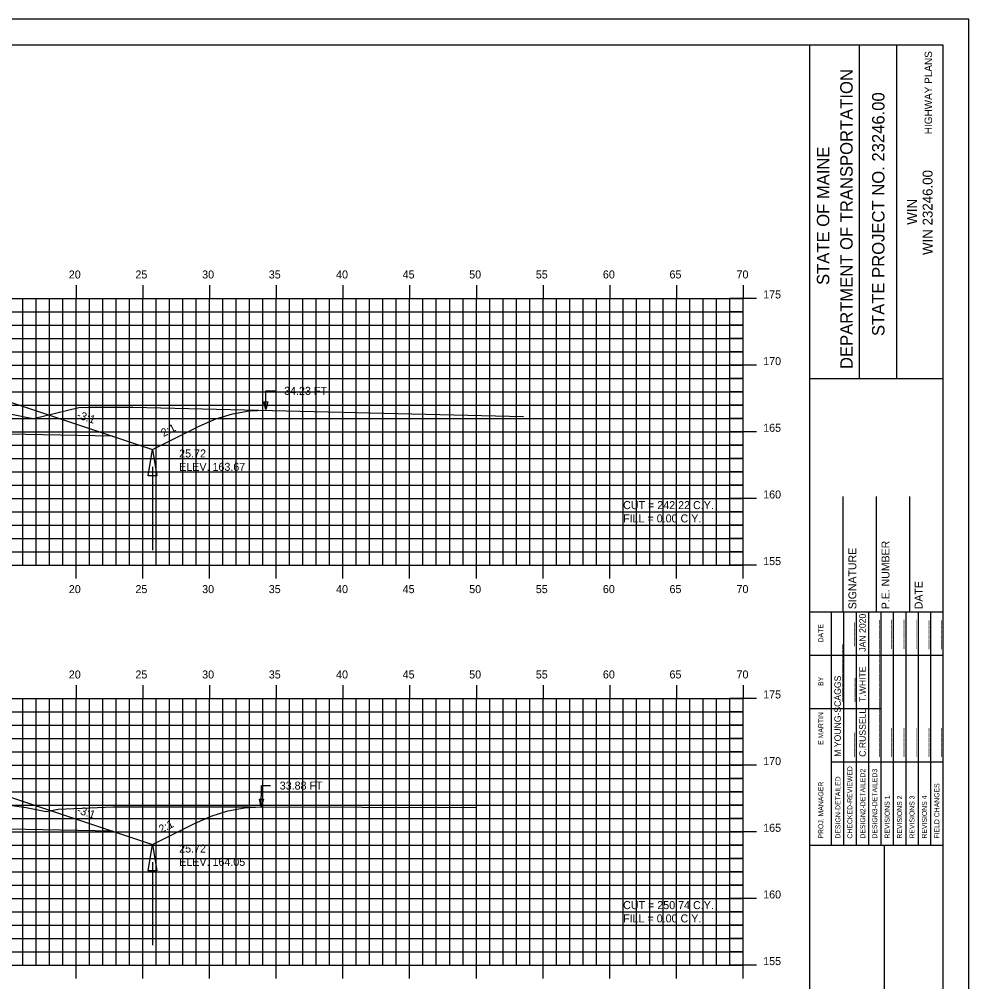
# Model space of a CAD drawing. Extents: x 1142089 to 1142259, y 608981 to 609091.
# Drawn here: x 1142188.3 to 1142259.4, y 609019.1 to 609091.3 of the extents above; entities that cross this region are included whole.
import ezdxf

# ---------------------------------------------------------------- set-up
doc = ezdxf.new("R2010")
doc.units = 0
for name, color, linetype in [('ANNOTATION', 7, 'Continuous'), ('BORDER', 7, 'Continuous'), ('D_Drainage_Ditch_Line', 7, 'Continuous'), ('D_Roadway_SlopeLines', 7, 'Continuous'), ('D_Roadway_SubGrade', 7, 'Continuous'), ('D_Text_Standard', 7, 'Continuous'), ('H_V ANNOTATION', 7, 'Continuous'), ('HIGHWAY_TITLE', 7, 'Continuous'), ('MAJOR', 7, 'Continuous'), ('MINOR', 7, 'Continuous'), ('PLOT BOUNDARY', 7, 'Continuous'), ('S_Roadway_Centerline', 7, 'Continuous')]:
    doc.layers.add(name, color=color, linetype=linetype)

msp = doc.modelspace()

# ---------------------------------------------------------------- linework, layer by layer
for points in [[(1142137.828, 609062.265), (1142139.078, 609062.182), (1142140.328, 609061.943), (1142141.578, 609061.55), (1142142.828, 609061.002), (1142146.816, 609059.009), (1142149.816, 609060.009), (1142157.539, 609062.583), (1142157.54, 609062.583), (1142161.54, 609062.743), (1142172.54, 609062.963), (1142183.54, 609062.743), (1142187.54, 609062.583), (1142195.264, 609060.009), (1142198.264, 609059.009), (1142201.765, 609060.76), (1142203.015, 609061.303), (1142204.265, 609061.682), (1142205.515, 609061.898), (1142206.765, 609061.95)], [(1142136.708, 609033.172), (1142137.958, 609033.099), (1142139.208, 609032.868), (1142140.458, 609032.48), (1142141.708, 609031.934), (1142146.816, 609029.38), (1142149.816, 609030.38), (1142157.539, 609032.955), (1142157.54, 609032.955), (1142161.54, 609033.115), (1142172.54, 609033.335), (1142183.54, 609033.115), (1142187.54, 609032.955), (1142195.264, 609030.38), (1142198.264, 609029.38), (1142201.423, 609030.96), (1142202.673, 609031.506), (1142203.923, 609031.896), (1142205.173, 609032.129), (1142206.423, 609032.206)]]:
    msp.add_lwpolyline(points)
at = {"layer": 'BORDER'}
for p, q in [((1142247.541, 608984.335), (1142247.541, 609089.335)), ((1142251.269, 609064.332), (1142251.269, 609089.332)), ((1142254.064, 609064.332), (1142254.064, 609089.332)), ((1142247.541, 609064.329), (1142257.541, 609064.329)), ((1142250.041, 609046.838), (1142250.041, 609055.485)), ((1142252.541, 609046.838), (1142252.541, 609055.485)), ((1142255.041, 609046.838), (1142255.041, 609055.485)), ((1142247.541, 609046.838), (1142257.541, 609046.838)), ((1142247.541, 609029.338), (1142257.541, 609029.338)), ((1142253.132, 608994.338), (1142253.132, 609029.338))]:
    msp.add_line(p, q, dxfattribs=at)
msp.add_lwpolyline([(1142097.541, 608984.335), (1142257.541, 608984.335), (1142257.541, 609089.335), (1142097.541, 609089.335)], close=True, dxfattribs=at)
for points in [[(1142249.155, 609043.588), (1142249.155, 609046.838)], [(1142250.088, 609029.341), (1142250.088, 609046.838)], [(1142251.02, 609046.838), (1142251.02, 609029.341)], [(1142251.951, 609029.341), (1142251.951, 609046.838)], [(1142252.883, 609029.341), (1142252.883, 609046.838)], [(1142253.815, 609029.341), (1142253.815, 609046.838)], [(1142254.746, 609029.341), (1142254.746, 609046.838)], [(1142255.678, 609029.341), (1142255.678, 609046.838)], [(1142256.61, 609029.341), (1142256.61, 609046.838)], [(1142249.156, 609029.341), (1142249.156, 609046.132)], [(1142247.541, 609043.588), (1142257.541, 609043.588)], [(1142247.541, 609039.588), (1142249.156, 609039.588)], [(1142249.155, 609039.588), (1142252.882, 609039.588)], [(1142249.155, 609035.588), (1142257.541, 609035.588)]]:
    msp.add_lwpolyline(points, dxfattribs=at)
at = {"layer": 'D_Drainage_Ditch_Line'}
for p, q in [((1142198.264, 609057.697), (1142198.263, 609051.453)), ((1142198.264, 609028.068), (1142198.263, 609021.824))]:
    msp.add_line(p, q, dxfattribs=at)
for points in [[(1142198.592, 609057.04), (1142197.936, 609057.04), (1142198.264, 609059.009)], [(1142198.592, 609027.412), (1142197.936, 609027.412), (1142198.264, 609029.38)]]:
    msp.add_lwpolyline(points, close=True, dxfattribs=at)
at = {"layer": 'D_Roadway_SlopeLines'}
for points in [[(1142198.264, 609059.009), (1142201.765, 609060.76), (1142203.015, 609061.303), (1142204.265, 609061.682), (1142205.515, 609061.898), (1142206.765, 609061.95)], [(1142195.264, 609060.009), (1142198.264, 609059.009)], [(1142198.264, 609029.38), (1142201.423, 609030.96), (1142202.673, 609031.506), (1142203.923, 609031.896), (1142205.173, 609032.129), (1142206.423, 609032.206)], [(1142195.264, 609030.38), (1142198.264, 609029.38)]]:
    msp.add_lwpolyline(points, dxfattribs=at)
at = {"layer": 'D_Roadway_SubGrade'}
for points in [[(1142183.54, 609062.327), (1142183.54, 609062.493), (1142187.54, 609062.333), (1142187.54, 609062.583), (1142187.54, 609062.583), (1142195.264, 609060.009), (1142183.54, 609060.243)], [(1142183.54, 609032.698), (1142183.54, 609032.865), (1142187.54, 609032.705), (1142187.54, 609032.955), (1142187.54, 609032.955), (1142195.264, 609030.38), (1142183.54, 609030.615)]]:
    msp.add_lwpolyline(points, close=True, dxfattribs=at)
at = {"layer": 'D_Text_Standard'}
for points in [[(1142206.765, 609062.01), (1142206.771, 609063.407), (1142207.451, 609063.407)], [(1142206.423, 609032.21), (1142206.442, 609033.799), (1142207.122, 609033.799)]]:
    msp.add_lwpolyline(points, dxfattribs=at)
for points in [[(1142206.765, 609062.01), (1142206.622, 609062.592), (1142206.913, 609062.591)], [(1142206.423, 609032.21), (1142206.284, 609032.793), (1142206.575, 609032.79)]]:
    msp.add_lwpolyline(points, close=True, dxfattribs=at)
at = {"layer": 'MAJOR'}
for p, q in [((1142192.54, 609071.337), (1142192.54, 609070.335)), ((1142197.54, 609071.337), (1142197.54, 609070.335)), ((1142202.54, 609071.337), (1142202.54, 609070.335)), ((1142207.54, 609071.337), (1142207.54, 609070.335)), ((1142212.54, 609071.337), (1142212.54, 609070.335)), ((1142217.54, 609071.337), (1142217.54, 609070.335)), ((1142222.54, 609071.337), (1142222.54, 609070.335)), ((1142227.54, 609071.337), (1142227.54, 609070.335)), ((1142232.54, 609071.337), (1142232.54, 609070.335)), ((1142237.54, 609071.337), (1142237.54, 609070.335)), ((1142242.54, 609071.337), (1142242.54, 609070.335)), ((1142102.54, 609070.335), (1142242.54, 609070.335)), ((1142102.54, 609070.335), (1142242.54, 609070.335)), ((1142192.54, 609050.335), (1142192.54, 609070.335)), ((1142197.54, 609050.335), (1142197.54, 609070.335)), ((1142202.54, 609050.335), (1142202.54, 609070.335)), ((1142207.54, 609050.335), (1142207.54, 609070.335)), ((1142212.54, 609050.335), (1142212.54, 609070.335)), ((1142217.54, 609050.335), (1142217.54, 609070.335)), ((1142222.54, 609050.335), (1142222.54, 609070.335)), ((1142227.54, 609050.335), (1142227.54, 609070.335)), ((1142232.54, 609050.335), (1142232.54, 609070.335)), ((1142237.54, 609050.335), (1142237.54, 609070.335)), ((1142243.542, 609070.335), (1142241.538, 609070.335)), ((1142242.54, 609050.335), (1142242.54, 609070.335)), ((1142242.54, 609050.335), (1142242.54, 609070.335)), ((1142102.54, 609065.335), (1142242.54, 609065.335)), ((1142243.542, 609065.335), (1142241.538, 609065.335)), ((1142102.54, 609060.335), (1142242.54, 609060.335)), ((1142243.542, 609060.335), (1142241.538, 609060.335)), ((1142102.54, 609055.335), (1142242.54, 609055.335)), ((1142243.542, 609055.335), (1142241.538, 609055.335)), ((1142102.54, 609050.335), (1142242.54, 609050.335)), ((1142102.54, 609050.335), (1142242.54, 609050.335)), ((1142192.54, 609049.333), (1142192.54, 609050.335)), ((1142197.54, 609049.333), (1142197.54, 609050.335)), ((1142202.54, 609049.333), (1142202.54, 609050.335)), ((1142207.54, 609049.333), (1142207.54, 609050.335)), ((1142212.54, 609049.333), (1142212.54, 609050.335)), ((1142217.54, 609049.333), (1142217.54, 609050.335)), ((1142222.54, 609049.333), (1142222.54, 609050.335)), ((1142227.54, 609049.333), (1142227.54, 609050.335)), ((1142232.54, 609049.333), (1142232.54, 609050.335)), ((1142237.54, 609049.333), (1142237.54, 609050.335)), ((1142243.542, 609050.335), (1142241.538, 609050.335)), ((1142242.54, 609049.333), (1142242.54, 609050.335)), ((1142192.54, 609041.337), (1142192.54, 609040.335)), ((1142197.54, 609041.337), (1142197.54, 609040.335)), ((1142202.54, 609041.337), (1142202.54, 609040.335)), ((1142207.54, 609041.337), (1142207.54, 609040.335)), ((1142212.54, 609041.337), (1142212.54, 609040.335)), ((1142217.54, 609041.337), (1142217.54, 609040.335)), ((1142222.54, 609041.337), (1142222.54, 609040.335)), ((1142227.54, 609041.337), (1142227.54, 609040.335)), ((1142232.54, 609041.337), (1142232.54, 609040.335)), ((1142237.54, 609041.337), (1142237.54, 609040.335)), ((1142242.54, 609041.337), (1142242.54, 609040.335)), ((1142102.54, 609040.335), (1142242.54, 609040.335)), ((1142102.54, 609040.335), (1142242.54, 609040.335)), ((1142192.54, 609020.335), (1142192.54, 609040.335)), ((1142197.54, 609020.335), (1142197.54, 609040.335)), ((1142202.54, 609020.335), (1142202.54, 609040.335)), ((1142207.54, 609020.335), (1142207.54, 609040.335)), ((1142212.54, 609020.335), (1142212.54, 609040.335)), ((1142217.54, 609020.335), (1142217.54, 609040.335)), ((1142222.54, 609020.335), (1142222.54, 609040.335)), ((1142227.54, 609020.335), (1142227.54, 609040.335)), ((1142232.54, 609020.335), (1142232.54, 609040.335)), ((1142237.54, 609020.335), (1142237.54, 609040.335)), ((1142243.542, 609040.335), (1142241.538, 609040.335)), ((1142242.54, 609020.335), (1142242.54, 609040.335)), ((1142242.54, 609020.335), (1142242.54, 609040.335)), ((1142102.54, 609035.335), (1142242.54, 609035.335)), ((1142243.542, 609035.335), (1142241.538, 609035.335)), ((1142102.54, 609030.335), (1142242.54, 609030.335)), ((1142243.542, 609030.335), (1142241.538, 609030.335)), ((1142102.54, 609025.335), (1142242.54, 609025.335)), ((1142243.542, 609025.335), (1142241.538, 609025.335)), ((1142102.54, 609020.335), (1142242.54, 609020.335)), ((1142102.54, 609020.335), (1142242.54, 609020.335)), ((1142192.54, 609019.333), (1142192.54, 609020.335)), ((1142197.54, 609019.333), (1142197.54, 609020.335)), ((1142202.54, 609019.333), (1142202.54, 609020.335)), ((1142207.54, 609019.333), (1142207.54, 609020.335)), ((1142212.54, 609019.333), (1142212.54, 609020.335)), ((1142217.54, 609019.333), (1142217.54, 609020.335)), ((1142222.54, 609019.333), (1142222.54, 609020.335)), ((1142227.54, 609019.333), (1142227.54, 609020.335)), ((1142232.54, 609019.333), (1142232.54, 609020.335)), ((1142237.54, 609019.333), (1142237.54, 609020.335)), ((1142243.542, 609020.335), (1142241.538, 609020.335)), ((1142242.54, 609019.333), (1142242.54, 609020.335))]:
    msp.add_line(p, q, dxfattribs=at)
at = {"layer": 'MINOR'}
for p, q in [((1142188.54, 609050.335), (1142188.54, 609070.335)), ((1142189.54, 609050.335), (1142189.54, 609070.335)), ((1142190.54, 609050.335), (1142190.54, 609070.335)), ((1142191.54, 609050.335), (1142191.54, 609070.335)), ((1142193.54, 609050.335), (1142193.54, 609070.335)), ((1142194.54, 609050.335), (1142194.54, 609070.335)), ((1142195.54, 609050.335), (1142195.54, 609070.335)), ((1142196.54, 609050.335), (1142196.54, 609070.335)), ((1142198.54, 609050.335), (1142198.54, 609070.335)), ((1142199.54, 609050.335), (1142199.54, 609070.335)), ((1142200.54, 609050.335), (1142200.54, 609070.335)), ((1142201.54, 609050.335), (1142201.54, 609070.335)), ((1142203.54, 609050.335), (1142203.54, 609070.335)), ((1142204.54, 609050.335), (1142204.54, 609070.335)), ((1142205.54, 609050.335), (1142205.54, 609070.335)), ((1142206.54, 609050.335), (1142206.54, 609070.335)), ((1142208.54, 609050.335), (1142208.54, 609070.335)), ((1142209.54, 609050.335), (1142209.54, 609070.335)), ((1142210.54, 609050.335), (1142210.54, 609070.335)), ((1142211.54, 609050.335), (1142211.54, 609070.335)), ((1142213.54, 609050.335), (1142213.54, 609070.335)), ((1142214.54, 609050.335), (1142214.54, 609070.335)), ((1142215.54, 609050.335), (1142215.54, 609070.335)), ((1142216.54, 609050.335), (1142216.54, 609070.335)), ((1142218.54, 609050.335), (1142218.54, 609070.335)), ((1142219.54, 609050.335), (1142219.54, 609070.335)), ((1142220.54, 609050.335), (1142220.54, 609070.335)), ((1142221.54, 609050.335), (1142221.54, 609070.335)), ((1142223.54, 609050.335), (1142223.54, 609070.335)), ((1142224.54, 609050.335), (1142224.54, 609070.335)), ((1142225.54, 609050.335), (1142225.54, 609070.335)), ((1142226.54, 609050.335), (1142226.54, 609070.335)), ((1142228.54, 609050.335), (1142228.54, 609070.335)), ((1142229.54, 609050.335), (1142229.54, 609070.335)), ((1142230.54, 609050.335), (1142230.54, 609070.335)), ((1142231.54, 609050.335), (1142231.54, 609070.335)), ((1142233.54, 609050.335), (1142233.54, 609070.335)), ((1142234.54, 609050.335), (1142234.54, 609070.335)), ((1142235.54, 609050.335), (1142235.54, 609070.335)), ((1142236.54, 609050.335), (1142236.54, 609070.335)), ((1142238.54, 609050.335), (1142238.54, 609070.335)), ((1142239.54, 609050.335), (1142239.54, 609070.335)), ((1142240.54, 609050.335), (1142240.54, 609070.335)), ((1142241.54, 609050.335), (1142241.54, 609070.335)), ((1142102.54, 609069.335), (1142242.54, 609069.335)), ((1142242.54, 609069.335), (1142241.538, 609069.335)), ((1142102.54, 609068.335), (1142242.54, 609068.335)), ((1142242.54, 609068.335), (1142241.538, 609068.335)), ((1142102.54, 609067.335), (1142242.54, 609067.335)), ((1142242.54, 609067.335), (1142241.538, 609067.335)), ((1142102.54, 609066.335), (1142242.54, 609066.335)), ((1142242.54, 609066.335), (1142241.538, 609066.335)), ((1142102.54, 609064.335), (1142242.54, 609064.335)), ((1142242.54, 609064.335), (1142241.538, 609064.335)), ((1142102.54, 609063.335), (1142242.54, 609063.335)), ((1142242.54, 609063.335), (1142241.538, 609063.335)), ((1142102.54, 609062.335), (1142242.54, 609062.335)), ((1142242.54, 609062.335), (1142241.538, 609062.335)), ((1142102.54, 609061.335), (1142242.54, 609061.335)), ((1142242.54, 609061.335), (1142241.538, 609061.335)), ((1142102.54, 609059.335), (1142242.54, 609059.335)), ((1142242.54, 609059.335), (1142241.538, 609059.335)), ((1142102.54, 609058.335), (1142242.54, 609058.335)), ((1142242.54, 609058.335), (1142241.538, 609058.335)), ((1142102.54, 609057.335), (1142242.54, 609057.335)), ((1142242.54, 609057.335), (1142241.538, 609057.335)), ((1142102.54, 609056.335), (1142242.54, 609056.335)), ((1142242.54, 609056.335), (1142241.538, 609056.335)), ((1142102.54, 609054.335), (1142242.54, 609054.335)), ((1142242.54, 609054.335), (1142241.538, 609054.335)), ((1142102.54, 609053.335), (1142242.54, 609053.335)), ((1142242.54, 609053.335), (1142241.538, 609053.335)), ((1142102.54, 609052.335), (1142242.54, 609052.335)), ((1142242.54, 609052.335), (1142241.538, 609052.335)), ((1142102.54, 609051.335), (1142242.54, 609051.335)), ((1142242.54, 609051.335), (1142241.538, 609051.335)), ((1142188.54, 609020.335), (1142188.54, 609040.335)), ((1142189.54, 609020.335), (1142189.54, 609040.335)), ((1142190.54, 609020.335), (1142190.54, 609040.335)), ((1142191.54, 609020.335), (1142191.54, 609040.335)), ((1142193.54, 609020.335), (1142193.54, 609040.335)), ((1142194.54, 609020.335), (1142194.54, 609040.335)), ((1142195.54, 609020.335), (1142195.54, 609040.335)), ((1142196.54, 609020.335), (1142196.54, 609040.335)), ((1142198.54, 609020.335), (1142198.54, 609040.335)), ((1142199.54, 609020.335), (1142199.54, 609040.335)), ((1142200.54, 609020.335), (1142200.54, 609040.335)), ((1142201.54, 609020.335), (1142201.54, 609040.335)), ((1142203.54, 609020.335), (1142203.54, 609040.335)), ((1142204.54, 609020.335), (1142204.54, 609040.335)), ((1142205.54, 609020.335), (1142205.54, 609040.335)), ((1142206.54, 609020.335), (1142206.54, 609040.335)), ((1142208.54, 609020.335), (1142208.54, 609040.335)), ((1142209.54, 609020.335), (1142209.54, 609040.335)), ((1142210.54, 609020.335), (1142210.54, 609040.335)), ((1142211.54, 609020.335), (1142211.54, 609040.335)), ((1142213.54, 609020.335), (1142213.54, 609040.335)), ((1142214.54, 609020.335), (1142214.54, 609040.335)), ((1142215.54, 609020.335), (1142215.54, 609040.335)), ((1142216.54, 609020.335), (1142216.54, 609040.335)), ((1142218.54, 609020.335), (1142218.54, 609040.335)), ((1142219.54, 609020.335), (1142219.54, 609040.335)), ((1142220.54, 609020.335), (1142220.54, 609040.335)), ((1142221.54, 609020.335), (1142221.54, 609040.335)), ((1142223.54, 609020.335), (1142223.54, 609040.335)), ((1142224.54, 609020.335), (1142224.54, 609040.335)), ((1142225.54, 609020.335), (1142225.54, 609040.335)), ((1142226.54, 609020.335), (1142226.54, 609040.335)), ((1142228.54, 609020.335), (1142228.54, 609040.335)), ((1142229.54, 609020.335), (1142229.54, 609040.335)), ((1142230.54, 609020.335), (1142230.54, 609040.335)), ((1142231.54, 609020.335), (1142231.54, 609040.335)), ((1142233.54, 609020.335), (1142233.54, 609040.335)), ((1142234.54, 609020.335), (1142234.54, 609040.335)), ((1142235.54, 609020.335), (1142235.54, 609040.335)), ((1142236.54, 609020.335), (1142236.54, 609040.335)), ((1142238.54, 609020.335), (1142238.54, 609040.335)), ((1142239.54, 609020.335), (1142239.54, 609040.335)), ((1142240.54, 609020.335), (1142240.54, 609040.335)), ((1142241.54, 609020.335), (1142241.54, 609040.335)), ((1142102.54, 609039.335), (1142242.54, 609039.335)), ((1142242.54, 609039.335), (1142241.538, 609039.335)), ((1142102.54, 609038.335), (1142242.54, 609038.335)), ((1142242.54, 609038.335), (1142241.538, 609038.335)), ((1142102.54, 609037.335), (1142242.54, 609037.335)), ((1142242.54, 609037.335), (1142241.538, 609037.335)), ((1142102.54, 609036.335), (1142242.54, 609036.335)), ((1142242.54, 609036.335), (1142241.538, 609036.335)), ((1142102.54, 609034.335), (1142242.54, 609034.335)), ((1142242.54, 609034.335), (1142241.538, 609034.335)), ((1142102.54, 609033.335), (1142242.54, 609033.335)), ((1142242.54, 609033.335), (1142241.538, 609033.335)), ((1142102.54, 609032.335), (1142242.54, 609032.335)), ((1142242.54, 609032.335), (1142241.538, 609032.335)), ((1142102.54, 609031.335), (1142242.54, 609031.335)), ((1142242.54, 609031.335), (1142241.538, 609031.335)), ((1142102.54, 609029.335), (1142242.54, 609029.335)), ((1142242.54, 609029.335), (1142241.538, 609029.335)), ((1142102.54, 609028.335), (1142242.54, 609028.335)), ((1142242.54, 609028.335), (1142241.538, 609028.335)), ((1142102.54, 609027.335), (1142242.54, 609027.335)), ((1142242.54, 609027.335), (1142241.538, 609027.335)), ((1142102.54, 609026.335), (1142242.54, 609026.335)), ((1142242.54, 609026.335), (1142241.538, 609026.335)), ((1142102.54, 609024.335), (1142242.54, 609024.335)), ((1142242.54, 609024.335), (1142241.538, 609024.335)), ((1142102.54, 609023.335), (1142242.54, 609023.335)), ((1142242.54, 609023.335), (1142241.538, 609023.335)), ((1142102.54, 609022.335), (1142242.54, 609022.335)), ((1142242.54, 609022.335), (1142241.538, 609022.335)), ((1142102.54, 609021.335), (1142242.54, 609021.335)), ((1142242.54, 609021.335), (1142241.538, 609021.335))]:
    msp.add_line(p, q, dxfattribs=at)
at = {"layer": 'PLOT BOUNDARY'}
msp.add_lwpolyline([(1142089.447, 608981.276), (1142259.447, 608981.276), (1142259.447, 609091.276), (1142089.447, 609091.276)], close=True, dxfattribs=at)
at = {"layer": 'S_Roadway_Centerline'}
for points in [[(1142121.499, 609062.314), (1142124.848, 609062.332), (1142147.197, 609062.217), (1142148.083, 609062.009), (1142152.294, 609061.364), (1142155.822, 609062.125), (1142156.149, 609062.208), (1142158.311, 609062.472), (1142158.759, 609062.53), (1142160.215, 609062.545), (1142170.281, 609062.669), (1142171.77, 609062.641), (1142181.503, 609062.327), (1142182.265, 609062.249), (1142185.613, 609062.083), (1142188.915, 609061.404), (1142189.355, 609061.342), (1142192.75, 609062.16), (1142193.47, 609062.189), (1142196.798, 609062.187), (1142226.066, 609061.493)], [(1142121.671, 609033.112), (1142126.127, 609033.122), (1142147.112, 609033.221), (1142148.27, 609032.961), (1142152.957, 609031.847), (1142153.787, 609031.981), (1142155.823, 609032.494), (1142156.613, 609032.611), (1142159.401, 609032.97), (1142168.323, 609033.066), (1142171.191, 609033.079), (1142179.536, 609032.919), (1142182.26, 609032.89), (1142183, 609032.834), (1142186.686, 609032.455), (1142188.804, 609032.159), (1142190.283, 609031.867), (1142191.191, 609032.024), (1142195.319, 609032.212), (1142205.426, 609032.209), (1142222.534, 609032.153)]]:
    msp.add_lwpolyline(points, dxfattribs=at)

# ---------------------------------------------------------------- texts
at = {"layer": 'ANNOTATION'}
for s, rotation, p in [('-3:1', 341.56521, (1142192.552, 609061.367)), ('2:1', 26.56505, (1142199.087, 609059.939)), ('-3:1', 341.56521, (1142192.552, 609031.738)), ('2:1', 26.56505, (1142198.916, 609030.224))]:
    msp.add_text(s, height=0.6, rotation=rotation, dxfattribs=at).set_placement(p)
at = {"layer": 'BORDER'}
for s, height, p in [('DEPARTMENT OF TRANSPORTATION', 0.93176, (1142250.747, 609065.041)), ('STATE PROJECT NO. 23246.00', 0.93176, (1142253.132, 609067.517)), ('STATE OF MAINE', 0.93176, (1142248.996, 609071.347)), ('WIN 23246.00', 0.74527, (1142256.736, 609073.596)), ('WIN', 0.7453, (1142255.577, 609075.865)), ('SIGNATURE', 0.5906, (1142251.021, 609047.03)), ('P.E. NUMBER', 0.59055, (1142253.501, 609047.03)), ('DATE', 0.5906, (1142255.982, 609047.03)), ('JAN 2020', 0.4845, (1142251.727, 609043.843)), ('DATE', 0.3714, (1142248.545, 609044.544)), ('_____', 0.4845, (1142250.758, 609044.243)), ('______', 0.4845, (1142252.621, 609044.063)), ('______', 0.4845, (1142253.553, 609044.065)), ('______', 0.4845, (1142254.485, 609044.067)), ('______', 0.4845, (1142255.416, 609044.067)), ('______', 0.4845, (1142256.348, 609044.036)), ('______', 0.4845, (1142257.28, 609044.036)), ('____________', 0.48455, (1142249.863, 609040.073)), ('____________', 0.48455, (1142252.621, 609040.073)), ('T.WHITE', 0.4845, (1142251.727, 609040.073)), ('BY', 0.3714, (1142248.545, 609041.273)), ('M YOUNG-SCAGGS', 0.48455, (1142249.863, 609035.961)), ('_____', 0.4845, (1142250.795, 609040.073)), ('____________', 0.48455, (1142252.621, 609035.961)), ('C.RUSSELL', 0.4845, (1142251.727, 609035.961)), ('E MARTIN', 0.3727, (1142248.545, 609036.855)), ('_____', 0.4845, (1142250.758, 609035.961)), ('______', 0.4845, (1142253.553, 609035.961)), ('______', 0.4845, (1142254.485, 609035.961)), ('______', 0.4845, (1142255.416, 609035.961)), ('______', 0.4845, (1142256.348, 609035.961)), ('______', 0.4845, (1142257.28, 609035.961)), ('CHECKED-REVIEWED', 0.37275, (1142250.722, 609029.826)), ('DESIGN2-DETAILED2', 0.37275, (1142251.69, 609029.826)), ('DESIGN3-DETAILED3', 0.37275, (1142252.585, 609029.826)), ('DESIGN-DETAILED', 0.37275, (1142249.827, 609029.826)), ('PROJ. MANAGER', 0.37275, (1142248.545, 609029.826)), ('FIELD CHANGES', 0.37275, (1142257.243, 609029.826)), ('REVISIONS 1', 0.37275, (1142253.517, 609029.826)), ('REVISIONS 2', 0.37275, (1142254.448, 609029.826)), ('REVISIONS 3', 0.37275, (1142255.38, 609029.826)), ('REVISIONS 4', 0.37275, (1142256.312, 609029.826))]:
    msp.add_text(s, height=height, rotation=90, dxfattribs=at).set_placement(p)
at = {"layer": 'D_Text_Standard'}
for s, p in [('34.23 FT', (1142208.131, 609063.107)), ('25.72', (1142200.264, 609058.409)), ('ELEV. 163.67', (1142200.264, 609057.407)), ('CUT = 242.22 C.Y.', (1142233.54, 609054.535)), ('FILL = 0.00 C.Y.', (1142233.54, 609053.539)), ('33.88 FT', (1142207.802, 609033.499)), ('25.72', (1142200.264, 609028.78)), ('ELEV. 164.05', (1142200.264, 609027.778)), ('CUT = 250.74 C.Y.', (1142233.54, 609024.535)), ('FILL = 0.00 C.Y.', (1142233.54, 609023.539))]:
    msp.add_text(s, height=0.6, dxfattribs=at).set_placement(p)
at = {"layer": 'H_V ANNOTATION'}
for s, p in [('20', (1142191.994, 609071.835)), ('25', (1142196.986, 609071.835)), ('30', (1142201.989, 609071.835)), ('35', (1142206.981, 609071.835)), ('40', (1142212.026, 609071.835)), ('45', (1142217.018, 609071.835)), ('50', (1142222.005, 609071.835)), ('55', (1142226.997, 609071.835)), ('60', (1142232.026, 609071.835)), ('65', (1142237.018, 609071.835)), ('70', (1142242.042, 609071.835)), ('175', (1142244.04, 609070.335)), ('170', (1142244.04, 609065.335)), ('165', (1142244.04, 609060.335)), ('160', (1142244.04, 609055.335)), ('155', (1142244.04, 609050.335)), ('20', (1142191.994, 609048.235)), ('25', (1142196.986, 609048.235)), ('30', (1142201.989, 609048.235)), ('35', (1142206.981, 609048.235)), ('40', (1142212.026, 609048.235)), ('45', (1142217.018, 609048.235)), ('50', (1142222.005, 609048.235)), ('55', (1142226.997, 609048.235)), ('60', (1142232.026, 609048.235)), ('65', (1142237.018, 609048.235)), ('70', (1142242.042, 609048.235)), ('20', (1142191.994, 609041.835)), ('25', (1142196.986, 609041.835)), ('30', (1142201.989, 609041.835)), ('35', (1142206.981, 609041.835)), ('40', (1142212.026, 609041.835)), ('45', (1142217.018, 609041.835)), ('50', (1142222.005, 609041.835)), ('55', (1142226.997, 609041.835)), ('60', (1142232.026, 609041.835)), ('65', (1142237.018, 609041.835)), ('70', (1142242.042, 609041.835)), ('175', (1142244.04, 609040.335)), ('170', (1142244.04, 609035.335)), ('165', (1142244.04, 609030.335)), ('160', (1142244.04, 609025.335)), ('155', (1142244.04, 609020.335))]:
    msp.add_text(s, height=0.6, dxfattribs=at).set_placement(p)
at = {"layer": 'HIGHWAY_TITLE'}
msp.add_text('HIGHWAY PLANS', height=0.55901, rotation=90, dxfattribs=at).set_placement((1142256.699, 609082.65))

doc.saveas('drawing.dxf')
